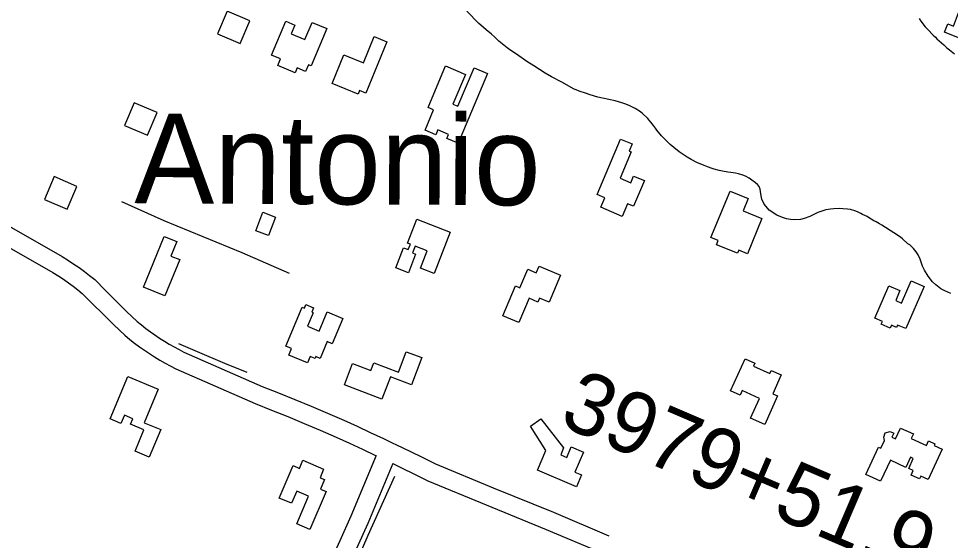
# Model space of a CAD drawing. Extents: x 3297735 to 3335592, y 670436 to 695807.
# Drawn here: x 3315202 to 3316711, y 693000 to 693844 of the extents above; entities that cross this region are included whole.
import ezdxf

# ---------------------------------------------------------------- set-up
doc = ezdxf.new("R2010")
doc.units = 0
for name, color, linetype in [('V-BLDG-OTLN', 7, 'Continuous'), ('V-RIVR-EDGE', 7, 'Continuous'), ('V-ROAD-CNTR', 7, 'Continuous'), ('V-SITE-VEGE', 7, 'Continuous'), ('V-SURV-IDEN', 7, 'Continuous'), ('V-TOPO-GNAM-IDEN', 7, 'Continuous'), ('V-TOPO-SHOR', 7, 'Continuous')]:
    doc.layers.add(name, color=color, linetype=linetype)

msp = doc.modelspace()

# ---------------------------------------------------------------- linework, layer by layer
at = {"layer": 'V-BLDG-OTLN'}
for points in [[(3315523.8, 693819.6), (3315560.6, 693803.9), (3315576.3, 693840.7), (3315539.5, 693856.4)], [(3316760.3, 693798.7), (3316701, 693822), (3316706.5, 693835.8), (3316715.6, 693832.1), (3316724.1, 693853.7), (3316762.9, 693838.5), (3316754.3, 693816.6), (3316765.6, 693812.2)], [(3315701.3, 693828), (3315675.8, 693767.6), (3315671.3, 693769.5), (3315666.7, 693758.5), (3315653, 693764.3), (3315649.8, 693756.4), (3315621.6, 693768.3), (3315626, 693778.9), (3315611.5, 693785), (3315634.7, 693839.9), (3315649.1, 693833.8), (3315643.1, 693819.5), (3315665.5, 693810.1), (3315677.3, 693838.1)], [(3315798.1, 693806.8), (3315764.2, 693723.6), (3315754.1, 693727.7), (3315751.6, 693721.8), (3315709.4, 693739), (3315728.3, 693785.5), (3315760.5, 693772.4), (3315777.9, 693815)], [(3315961.2, 693755.3), (3315913.7, 693642.7), (3315895.6, 693650.3), (3315898.2, 693656.5), (3315880.6, 693663.9), (3315877.3, 693656.1), (3315860, 693663.4), (3315873.9, 693696.6), (3315865.1, 693700.3), (3315893.4, 693767.5), (3315925.5, 693753.9), (3315905.2, 693705.8), (3315913.2, 693702.4), (3315939.4, 693764.5)], [(3315373.6, 693671.1), (3315410.4, 693655.4), (3315426.1, 693692.2), (3315389.3, 693707.9)], [(3316138.6, 693559.6), (3316176.8, 693649.3), (3316195.6, 693641.3), (3316190.7, 693629.8), (3316194, 693628.4), (3316175.9, 693585.8), (3316193.1, 693578.4), (3316197.8, 693589.4), (3316215.2, 693582), (3316197.6, 693540.5), (3316188, 693544.6), (3316179.3, 693524.1), (3316144.5, 693539), (3316151, 693554.3)], [(3315243.9, 693551.6), (3315280.7, 693535.9), (3315296.4, 693572.7), (3315259.6, 693588.4)], [(3316405.5, 693520.5), (3316382.2, 693463.6), (3316368.1, 693469.4), (3316366, 693464.4), (3316332.2, 693478.3), (3316334.9, 693484.9), (3316323, 693489.8), (3316353.9, 693565), (3316383.3, 693553), (3316375.1, 693532.9)], [(3315586, 693500.7), (3315597.3, 693530.7), (3315617.7, 693523), (3315606.4, 693493)], [(3315846.8, 693519.7), (3315900.8, 693498.6), (3315874.8, 693431.7), (3315852.6, 693440.3), (3315863.5, 693468.3), (3315843.9, 693476), (3315839.6, 693465), (3315844.8, 693462.9), (3315833.1, 693432.9), (3315812.7, 693440.8), (3315825.3, 693473.4), (3315833, 693470.4), (3315836.5, 693479.2), (3315831.8, 693481)], [(3315438.9, 693395.5), (3315404.1, 693409.6), (3315437.4, 693491.6), (3315457.9, 693483.2), (3315448.5, 693459.9), (3315462.8, 693454.1)], [(3316028.4, 693391.6), (3316011.7, 693352.1), (3315986.1, 693362.9), (3316006.7, 693411.6), (3316013.7, 693408.6), (3316026.4, 693438.6), (3316040.1, 693432.8), (3316044.7, 693443.6), (3316079.5, 693428.9), (3316061.1, 693385.1), (3316045.4, 693391.7), (3316042.8, 693385.5)], [(3316668.2, 693410.5), (3316638.5, 693342.5), (3316625.1, 693348.3), (3316623.4, 693344.3), (3316615.5, 693347.8), (3316613.4, 693343), (3316598.7, 693349.5), (3316600.7, 693354.1), (3316588.4, 693359.5), (3316611.2, 693411.7), (3316629.1, 693403.9), (3316622.2, 693388.1), (3316631.8, 693383.9), (3316647.4, 693419.6)], [(3315634.6, 693314.1), (3315660.9, 693376.9), (3315664.7, 693375.3), (3315667.2, 693381.3), (3315679.4, 693376.2), (3315676.5, 693369.2), (3315678.9, 693368.2), (3315669.8, 693346.3), (3315688.8, 693338.3), (3315701.8, 693369.5), (3315727, 693359), (3315709.9, 693318), (3315701.5, 693321.5), (3315690.2, 693294.3), (3315683.4, 693297.1), (3315682.2, 693294.2), (3315674.2, 693297.5), (3315669.8, 693287), (3315639.6, 693299.7), (3315644, 693310.2)], [(3315742.7, 693286.1), (3315772.3, 693274.8), (3315777, 693287.2), (3315817.1, 693271.9), (3315829.7, 693305), (3315854.7, 693295.5), (3315837.9, 693251.4), (3315804.1, 693264.4), (3315790.2, 693228.1), (3315729.4, 693251.4)], [(3316401.8, 693229.4), (3316373.8, 693242.1), (3316370.5, 693234.9), (3316354.8, 693241.9), (3316378.2, 693293.8), (3316394.1, 693286.6), (3316391.9, 693281.7), (3316418.4, 693269.8), (3316420.7, 693274.9), (3316436.9, 693267.6), (3316423.1, 693237), (3316431, 693233.5), (3316410.1, 693187), (3316387.3, 693197.3)], [(3315378.8, 693264.9), (3315428, 693244.3), (3315405.4, 693190.2), (3315432, 693179.1), (3315413.3, 693134.4), (3315390.4, 693143.9), (3315404.9, 693178.5), (3315383.3, 693187.6), (3315387, 693196.4), (3315373.3, 693202.2), (3315367.7, 693188.8), (3315350.1, 693196.2)], [(3316105.1, 693086.5), (3316042.3, 693113.2), (3316055.9, 693145.3), (3316030.8, 693184.5), (3316047.7, 693196.7), (3316084.5, 693149.7), (3316079.8, 693138), (3316089.5, 693133.9), (3316096.8, 693151), (3316116.6, 693142.7), (3316102.8, 693110.3), (3316113.3, 693105.9)], [(3316697.5, 693147.2), (3316674.8, 693098.1), (3316663.1, 693103.6), (3316661, 693099.1), (3316647.2, 693105.5), (3316650.6, 693112.8), (3316643.2, 693116.3), (3316650.6, 693132.3), (3316646.2, 693134.4), (3316638.6, 693117.9), (3316613.6, 693129.5), (3316597.8, 693095.5), (3316574, 693106.5), (3316594.4, 693150.5), (3316598.1, 693148.8), (3316604, 693161.4), (3316603.2, 693166.5), (3316605, 693174), (3316613.1, 693176.1), (3316619, 693173.4), (3316616, 693166.9), (3316622, 693164.2), (3316630.1, 693181.6), (3316650.9, 693172), (3316647.5, 693164.7), (3316672, 693153.3), (3316675.5, 693160.8), (3316685.7, 693156), (3316684.4, 693153.2)], [(3315699.9, 693078.7), (3315673.6, 693017.5), (3315652.3, 693026.7), (3315671.4, 693071.4), (3315652.2, 693079.6), (3315643.7, 693059.7), (3315624.1, 693068.2), (3315646.6, 693120.7), (3315656.7, 693116.3), (3315662.2, 693129.3), (3315695.9, 693114.8), (3315690, 693101.2), (3315697.5, 693098), (3315690.9, 693082.6)]]:
    msp.add_lwpolyline(points, close=True, dxfattribs=at)
at = {"layer": 'V-RIVR-EDGE'}
msp.add_spline([(3319555.1, 694014.6), (3319548.5, 694002.8), (3319539.4, 693985.8), (3319509.8, 693923.3), (3319496.5, 693903), (3319479.4, 693878.2), (3319464, 693854.6), (3319445.3, 693819), (3319424.4, 693775.5), (3319406.5, 693740.7), (3319395.7, 693713), (3319386.5, 693693.1), (3319372.8, 693671.6), (3319340.3, 693621.5), (3319316.6, 693580.1), (3319295.8, 693542.9), (3319282.1, 693521), (3319271.7, 693502.3), (3319267.9, 693489.5), (3319260, 693475.8), (3319250.4, 693465.1), (3319246.2, 693454.3), (3319237.9, 693442.3), (3319231.7, 693428.7), (3319225.4, 693415), (3319219.6, 693410), (3319205.5, 693391.4), (3319185.1, 693363.3), (3319164.7, 693327.7), (3319143.1, 693301.2), (3319109.4, 693253.2), (3319083.6, 693218.5), (3319061.1, 693187.8), (3319039.5, 693157.6), (3319018.3, 693123.3), (3318994.6, 693091), (3318949.7, 693031.9), (3318931.4, 693004.6), (3318913.1, 692981.4), (3318902.3, 692962.8), (3318892.7, 692944.5), (3318876, 692916.4), (3318861.9, 692887.8), (3318841.5, 692848.5), (3318822.3, 692807.5), (3318806.5, 692774.4), (3318803.1, 692758.7), (3318804.3, 692745), (3318808, 692734.6), (3318808.8, 692730.5), (3318817.1, 692725.5), (3318826.6, 692719.2), (3318832.8, 692713), (3318835.7, 692705.5), (3318835.3, 692692.3), (3318829.9, 692681.5), (3318819.9, 692669.1), (3318809.5, 692651.3), (3318783.2, 692602.9), (3318768.7, 692580.5), (3318760.8, 692576), (3318753.7, 692573.1), (3318747.1, 692573.9), (3318739.2, 692579.8), (3318735.5, 692585.6), (3318730.6, 692588.5), (3318721.4, 692588.1), (3318700.3, 692573.6), (3318679.5, 692549.7), (3318660.8, 692522.3), (3318646.6, 692493.4), (3318637, 692477.6), (3318625, 692456.9), (3318607.1, 692434.2), (3318600, 692413.5), (3318583.3, 692372.5), (3318565.8, 692342.3), (3318547.1, 692313.7), (3318534.2, 692295.5), (3318512.6, 692258.7), (3318488, 692224.8), (3318446.4, 692155.2), (3318418.1, 692112.6), (3318397.3, 692084.5), (3318386.9, 692066.7), (3318376.5, 692048), (3318354.4, 692011.2), (3318333.2, 691976.5), (3318316.1, 691940), (3318301.6, 691917.7), (3318275.4, 691885), (3318265.8, 691873), (3318250.8, 691844.8), (3318236.6, 691808.4), (3318222.1, 691781.1), (3318195, 691714), (3318180, 691684.2), (3318162.1, 691654.8), (3318140.8, 691619.6), (3318130.4, 691603.9), (3318120.9, 691595.2), (3318105.1, 691577.9), (3318090.1, 691558.4), (3318067.7, 691532.4), (3318043.6, 691501.8), (3318020.3, 691465.8), (3317998.2, 691433.1), (3317973.7, 691392.9), (3317962.4, 691371.8), (3317929.9, 691315.1), (3317907.9, 691282.4), (3317889.2, 691263.4), (3317870.5, 691238.2), (3317844.7, 691203), (3317833.1, 691186), (3317808.1, 691148.8), (3317780.6, 691109.5), (3317756.1, 691076.4), (3317732, 691045.3), (3317684.6, 690978.7), (3317668.8, 690954.7), (3317646.3, 690922), (3317635.5, 690907.1), (3317629.2, 690900.5), (3317620.1, 690889.4), (3317608.5, 690874.5), (3317601.4, 690867), (3317592.7, 690860.4), (3317585.6, 690845.9), (3317576.9, 690836), (3317565.6, 690821.1), (3317549.4, 690801.3), (3317522.4, 690767.7), (3317502.4, 690745), (3317490, 690727.6), (3317482.5, 690713.5), (3317479.5, 690701.1), (3317475.8, 690689.9), (3317474.9, 690683.3), (3317467.9, 690674.2), (3317451.7, 690653.9), (3317427.5, 690622.9), (3317406.3, 690594), (3317381.8, 690564.6), (3317328.2, 690504.6), (3317308.2, 690483.1), (3317290.8, 690466.2), (3317272.5, 690446.3), (3317248.8, 690422.7), (3317230.9, 690402.5), (3317202.2, 690356.5), (3317170.2, 690314.3), (3317129.5, 690266.4), (3317099.1, 690227.5), (3317085.8, 690212.6), (3317074.2, 690204.3), (3317063.4, 690189.8), (3317045.1, 690163.8), (3317020.9, 690128.6), (3316996.8, 690093.9), (3316970.6, 690059.1), (3316927, 690008.2), (3316891.7, 689970.6), (3316861.7, 689930.1), (3316828, 689887.9), (3316809.3, 689860.1), (3316797.2, 689841.9), (3316783.5, 689825.4), (3316737.4, 689762.1), (3316714.9, 689729), (3316681.6, 689687.6), (3316661.7, 689665.7), (3316648, 689646.7), (3316619.7, 689606.1), (3316602.6, 689581.3), (3316583.5, 689551.9), (3316563.9, 689519.6), (3316547.7, 689499.3), (3316541.9, 689491.9), (3316538.6, 689488.6), (3316532.3, 689474.1), (3316523.2, 689461.3), (3316509, 689445.1), (3316500.3, 689431.5), (3316493.2, 689419.9), (3316485.7, 689407.9), (3316486.1, 689397.1), (3316486.5, 689375.6), (3316487.3, 689371), (3316491.4, 689370.2), (3316493.5, 689366.4), (3316494.3, 689352.8), (3316496.8, 689341.6), (3316502.5, 689336.6), (3316504.2, 689334.1), (3316504.2, 689328.7), (3316501.3, 689325.8), (3316488.8, 689321.3), (3316487.2, 689319.6), (3316487.2, 689316.7), (3316493, 689316.7), (3316502.1, 689318.3), (3316508.3, 689318.3), (3316513.3, 689315), (3316516.6, 689315), (3316524.9, 689314.5), (3316535.6, 689303.3), (3316544.7, 689293.4), (3316545.5, 689290), (3316543.5, 689288), (3316525.7, 689296.7), (3316509.9, 689304.2), (3316502.1, 689307.1), (3316490.5, 689308.4), (3316482.6, 689308), (3316478, 689308), (3316473.5, 689311.8), (3316449.5, 689323.9), (3316424.6, 689324.7), (3316401.8, 689323.1), (3316381.5, 689318.2), (3316366.5, 689316.2), (3316352.9, 689311.2), (3316334.2, 689295.5), (3316302.2, 689277.8), (3316275.2, 689257.1), (3316266.5, 689249.3), (3316249, 689224), (3316230.3, 689191.8), (3316217.8, 689162.8), (3316200.7, 689125.9), (3316182.4, 689092.8), (3316162.8, 689054.7), (3316141.2, 689024.9), (3316114.6, 688996.4), (3316081.8, 688971.6), (3316036.9, 688926.1), (3316007.4, 688897.6), (3315987, 688880.7), (3315970, 688865.8), (3315959.6, 688858.8), (3315957.1, 688852.1), (3315955.5, 688848.4), (3315953.9, 688835.5)], degree=3, dxfattribs=at)
at = {"layer": 'V-ROAD-CNTR'}
for points in [[(3315152, 693527.8), (3315272.2, 693459), (3315282.7, 693452.9), (3315291.6, 693447), (3315300.1, 693441.1), (3315308.4, 693435), (3315316.6, 693428.6), (3315325.2, 693421.7), (3315342.7, 693403.9), (3315359.7, 693387), (3315376.9, 693370.3), (3315394, 693354.1), (3315400.8, 693348.5), (3315408, 693342.9), (3315415.3, 693337.5), (3315422.7, 693332.2), (3315430.3, 693327.1), (3315438, 693322.2), (3315445.8, 693317.4), (3315453.7, 693312.9), (3315461.7, 693308.5), (3315469.5, 693304.4), (3315596.4, 693248.9), (3315622.8, 693238.5), (3315649.3, 693227.8), (3315675.8, 693216.8), (3315702.2, 693205.5), (3315728.5, 693194.1), (3315750, 693184.3), (3315771.4, 693174.5), (3315792.8, 693164.5), (3315806.8, 693157.8), (3315814.1, 693154.3), (3315835.3, 693144.1), (3315856.5, 693133.7), (3315877.1, 693123.4), (3315970.5, 693084.8), (3316067.9, 693045.3), (3316157.8, 693007)], [(3315137.1, 693501.8), (3315257.3, 693433), (3315266.9, 693427.4), (3315274.7, 693422.3), (3315282.6, 693416.7), (3315290.4, 693411), (3315298, 693405.1), (3315305, 693399.4), (3315321.4, 693382.8), (3315338.7, 693365.6), (3315356.2, 693348.7), (3315374.1, 693331.6), (3315382, 693325.1), (3315389.8, 693319.1), (3315397.7, 693313.2), (3315405.7, 693307.5), (3315413.8, 693302), (3315422.1, 693296.7), (3315430.5, 693291.6), (3315439, 693286.7), (3315447.6, 693282), (3315456.6, 693277.3), (3315584.9, 693221.2), (3315611.6, 693210.7), (3315638, 693200), (3315664.2, 693189.1), (3315690.3, 693178), (3315716.3, 693166.6), (3315737.6, 693157), (3315758.8, 693147.3), (3315780, 693137.3), (3315781.1, 693136.8)], [(3315781, 693136.9), (3315740.1, 693039.1), (3315722, 692999), (3315703.8, 692958.4), (3315693.2, 692933.2), (3315683.2, 692908.7), (3315668, 692873.1)], [(3315808.1, 693123.9), (3315767.6, 693027.2), (3315749.3, 692986.7), (3315731.3, 692946.5), (3315720.9, 692921.8), (3315710.9, 692897.1), (3315695.6, 692861.3)], [(3315807.7, 693124.1), (3315822.2, 693117.1), (3315843.2, 693106.8), (3315864.6, 693096.1), (3315959.1, 693057), (3316056.4, 693017.6), (3316146.1, 692979.4)]]:
    msp.add_lwpolyline(points, dxfattribs=at)
at = {"layer": 'V-SITE-VEGE'}
for p, q in [((3315947.1, 693836), (3315927.7, 693856.1)), ((3316660.4, 693844.1), (3316663, 693839.9)), ((3315950.5, 693833.3), (3315947.1, 693836)), ((3315958.9, 693826.2), (3315950.5, 693833.3)), ((3316663, 693839.9), (3316670.1, 693830.9)), ((3316670.1, 693830.9), (3316674.1, 693826.4)), ((3315967.6, 693819.1), (3315958.9, 693826.2)), ((3315972.6, 693814.5), (3315967.6, 693819.1)), ((3315979.8, 693807.6), (3315972.6, 693814.5)), ((3316674.1, 693826.4), (3316683.1, 693817.2)), ((3316683.1, 693817.2), (3316686.6, 693814.1)), ((3316686.6, 693814.1), (3316689, 693811.6)), ((3315993.2, 693797), (3315979.8, 693807.6)), ((3315997.5, 693793.7), (3315993.2, 693797)), ((3316689, 693811.6), (3316696.6, 693804.7)), ((3316696.6, 693804.7), (3316699.9, 693802)), ((3316699.9, 693802), (3316705.2, 693797)), ((3316705.2, 693797), (3316709.3, 693793.4)), ((3316008, 693786.4), (3315997.5, 693793.7)), ((3316025.1, 693775), (3316008, 693786.4)), ((3316709.3, 693793.4), (3316717.2, 693787.2)), ((3316036.2, 693768), (3316025.1, 693775)), ((3316054.5, 693756), (3316036.2, 693768)), ((3316065.1, 693749.9), (3316054.5, 693756)), ((3316081.6, 693741.2), (3316065.1, 693749.9)), ((3316101.4, 693730.1), (3316081.6, 693741.2)), ((3316104.8, 693728.9), (3316101.4, 693730.1)), ((3316109.8, 693726.9), (3316104.8, 693728.9)), ((3316119.9, 693723.3), (3316109.8, 693726.9)), ((3316127.5, 693720.9), (3316119.9, 693723.3)), ((3316139.6, 693717.3), (3316127.5, 693720.9)), ((3316147.5, 693715.4), (3316139.6, 693717.3)), ((3316168, 693710.9), (3316147.5, 693715.4)), ((3316178.6, 693707.8), (3316168, 693710.9)), ((3316185.2, 693705.6), (3316178.6, 693707.8)), ((3316191.5, 693702.9), (3316185.2, 693705.6)), ((3316200.4, 693698.8), (3316191.5, 693702.9)), ((3316207.3, 693694.5), (3316200.4, 693698.8)), ((3316211.5, 693691.4), (3316207.3, 693694.5)), ((3316220.7, 693682.6), (3316211.5, 693691.4)), ((3316228, 693674), (3316220.7, 693682.6)), ((3316229.9, 693671.1), (3316228, 693674)), ((3316233.3, 693666.6), (3316229.9, 693671.1)), ((3316235.5, 693663.5), (3316233.3, 693666.6)), ((3316243, 693654.4), (3316235.5, 693663.5)), ((3316257, 693640.6), (3316243, 693654.4)), ((3316262.9, 693635.6), (3316257, 693640.6)), ((3316271.6, 693628.6), (3316262.9, 693635.6)), ((3316274.7, 693626.3), (3316271.6, 693628.6)), ((3316284.5, 693619.9), (3316274.7, 693626.3)), ((3316291, 693616.2), (3316284.5, 693619.9)), ((3316300.1, 693611.5), (3316291, 693616.2)), ((3316312.2, 693606.6), (3316300.1, 693611.5)), ((3316314.8, 693605.4), (3316312.2, 693606.6)), ((3316323.4, 693601.9), (3316314.8, 693605.4)), ((3316328.2, 693600.3), (3316323.4, 693601.9)), ((3316336.4, 693598.2), (3316328.2, 693600.3)), ((3316341.8, 693597), (3316336.4, 693598.2)), ((3316350.1, 693595.9), (3316341.8, 693597)), ((3316355.3, 693595), (3316350.1, 693595.9)), ((3316363, 693594.3), (3316355.3, 693595)), ((3316367.8, 693593.1), (3316363, 693594.3)), ((3316374.9, 693590.9), (3316367.8, 693593.1)), ((3316379, 693589.1), (3316374.9, 693590.9)), ((3316384.8, 693585.8), (3316379, 693589.1)), ((3316389.2, 693582.9), (3316384.8, 693585.8)), ((3316395.3, 693578.4), (3316389.2, 693582.9)), ((3316398.6, 693575.7), (3316395.3, 693578.4)), ((3316401, 693572.7), (3316398.6, 693575.7)), ((3316402.8, 693568), (3316401, 693572.7)), ((3316403.5, 693564.4), (3316402.8, 693568)), ((3316404.4, 693557.2), (3316403.5, 693564.4)), ((3316405.6, 693551.8), (3316404.4, 693557.2)), ((3316409.4, 693544), (3316405.6, 693551.8)), ((3316412.5, 693540), (3316409.4, 693544)), ((3316417.5, 693534.3), (3316412.5, 693540)), ((3316429.7, 693526.3), (3316417.5, 693534.3)), ((3316439, 693522.2), (3316429.7, 693526.3)), ((3316496.2, 693530.6), (3316482.9, 693524.1)), ((3316504.1, 693533.2), (3316496.2, 693530.6)), ((3316509, 693534.6), (3316504.1, 693533.2)), ((3316516.6, 693535.8), (3316509, 693534.6)), ((3316522.2, 693536.4), (3316516.6, 693535.8)), ((3316530.8, 693536.6), (3316522.2, 693536.4)), ((3316536.5, 693536.5), (3316530.8, 693536.6)), ((3316544.3, 693535.8), (3316536.5, 693536.5)), ((3316548.8, 693535.1), (3316544.3, 693535.8)), ((3316556.1, 693532.9), (3316548.8, 693535.1)), ((3316560.2, 693531.3), (3316556.1, 693532.9)), ((3316565.6, 693528.6), (3316560.2, 693531.3)), ((3316568.2, 693527.2), (3316565.6, 693528.6)), ((3316576, 693523.7), (3316568.2, 693527.2)), ((3316445.3, 693520), (3316439, 693522.2)), ((3316451.9, 693518.9), (3316445.3, 693520)), ((3316458.6, 693518.4), (3316451.9, 693518.9)), ((3316468, 693519), (3316458.6, 693518.4)), ((3316474.2, 693520.5), (3316468, 693519)), ((3316482.9, 693524.1), (3316474.2, 693520.5)), ((3316579.7, 693521.2), (3316576, 693523.7)), ((3316582.3, 693519.8), (3316579.7, 693521.2)), ((3316586.7, 693517.1), (3316582.3, 693519.8)), ((3316590.4, 693515.3), (3316586.7, 693517.1)), ((3316595.8, 693511.8), (3316590.4, 693515.3)), ((3316599.7, 693509.7), (3316595.8, 693511.8)), ((3316619.2, 693497.7), (3316599.7, 693509.7)), ((3316630.1, 693490.3), (3316619.2, 693497.7)), ((3316633.4, 693487.8), (3316630.1, 693490.3)), ((3316642.1, 693479.9), (3316633.4, 693487.8)), ((3316645.2, 693478), (3316642.1, 693479.9)), ((3316648, 693475.3), (3316645.2, 693478)), ((3316650.9, 693472.1), (3316648, 693475.3)), ((3316655.5, 693466.5), (3316650.9, 693472.1)), ((3316658.4, 693462), (3316655.5, 693466.5)), ((3316661.8, 693455.1), (3316658.4, 693462)), ((3316665.7, 693443.6), (3316661.8, 693455.1)), ((3316668.6, 693437), (3316665.7, 693443.6)), ((3316674.7, 693427.1), (3316668.6, 693437)), ((3316681.9, 693418.3), (3316674.7, 693427.1)), ((3316687, 693413.2), (3316681.9, 693418.3)), ((3316695.2, 693407), (3316687, 693413.2)), ((3316701.5, 693403.7), (3316695.2, 693407)), ((3316711.5, 693399.5), (3316701.5, 693403.7))]:
    msp.add_line(p, q, dxfattribs=at)
at = {"layer": 'V-TOPO-SHOR'}
for points in [[(3315640.8, 693431.4), (3315564, 693465.1), (3315437.5, 693516.9), (3315369.2, 693547.6)], [(3315572.1, 693271.3), (3315535.7, 693286.2), (3315491.5, 693304.9), (3315461.4, 693318)], [(3315722.9, 692901.8), (3315740.5, 692944.3), (3315768, 693007.9), (3315811, 693103.7)]]:
    msp.add_lwpolyline(points, dxfattribs=at)

# ---------------------------------------------------------------- texts
at = {"layer": 'V-SURV-IDEN'}
msp.add_text('3979+51.9', height=100, rotation=336.8188, dxfattribs=at).set_placement((3316074.4, 693187.8))
at = {"layer": 'V-TOPO-GNAM-IDEN'}
msp.add_text('Antonio', height=145, rotation=359.6879, dxfattribs=at).set_placement((3315389.3, 693545.5))

doc.saveas('drawing.dxf')
